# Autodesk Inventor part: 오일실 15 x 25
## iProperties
IsCustomPart: 0
Created: 2009-02
Part Number: 오일실 15 x 25
Material: 고무
Description: 오일-실
Document SubType Name: Modeling
Standard: KS B 2804
Designer: SeoGD™
Standards Organization: KS
Language: ko-KR
Size Designation: S - 15 25 7
Categories: <MemberInstance><Categories><Category DisplayName="샤프트 부품" InternalName="7f7aeb1f-a693-4053-b835-cee3144e0d98" Mnemonic="SHFT"><Category DisplayName="실링" Intern
Density: 0.93 g/cm^3
Author: SeoGD™
